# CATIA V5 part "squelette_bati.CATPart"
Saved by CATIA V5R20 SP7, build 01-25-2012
Part number: squelette_bati
Publications: "CK", "KF", "axe.pivot.F", "axe.pivot.K", "axe.pivot.C", "Plan.bati", "machoires.a'", "Ca'", "machoires.aa'", "machoires.a"
Bounding box of the stored display mesh (mm): x -24.1 to -2, y -58 to 18.5, z -8.5 to 56.5
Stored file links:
  F:\IAO\Catia\squelette_bati.CATPart
  F:\IAO\Catia\squelette.CATProduct
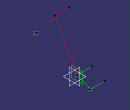
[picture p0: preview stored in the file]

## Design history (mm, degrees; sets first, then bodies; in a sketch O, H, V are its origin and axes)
Set1
  Point1 "C": linked copy from another document
  Point2 "K": linked copy from another document
  Point3 "F": linked copy from another document
  Plane1 "plan.bati": linked copy from another document
  Point4 "machoires.a": linked copy from another document
Set2
  Line1 "CK": type PtPt, FirstPoint Point1, SecondPoint Point2
  Line2 "KF": type PtPt, FirstPoint Point2, SecondPoint Point3
  Line3 "axe.pivot.F": type Normal, RefPoint Point3, RefSkin Plane1, Start 0, End 20
  Line4 "axe.pivot.K": type Normal, RefPoint Point2, RefSkin Plane1, Start 0, End 20
  Line5 "axe.pivot.C": type Normal, RefPoint Point1, RefSkin Plane1, Start 0, End 20
  Plane2 "Plan.bati": type Offset, RefPlane Plane1, Offset 0
  Point5 "machoires.a'": type OnPlane, Support Plane2, H -58, V 22.5, Direction (0, 1, 0)
  Line6 "machoires.aa'": type PtPt, FirstPoint Point5, SecondPoint Point4
  Line7 "Ca'": type PtPt, FirstPoint Point1, SecondPoint Point5
  Point6 "machoires.a": (0, 0, 0), relative to Point4
Body1 (main body)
